(* Logix 5000 project; controller NXEE2_EDS_AOI_Sample_RSLogix_V31 vendor 1 type 14 code 108 rev 31.11; software revision 31.02 *)

TASK MainTask (continuous, watchdog 500 ms) : MainProgram

MODULES
   Local : vendor 1 type 14 code 108 (Compact 0, rev 31.11)
      AMCI_EDS_NXEE2 : vendor 10 type 12 code 50 (Ethernet 192.168.0.50, rev 1.21, StandardDataDriven RPI 8 ms)
END_MODULES

TYPE AMCI_NXEE2_Input_Data :
STRUCT
   Word_0_Reserved_Bit_0 : BOOL;
   Word_0_Reserved_Bit_1 : BOOL;
   CH1_Motion_Detection : BOOL;
   CH1_Velocity_at_Zero : BOOL;
   CH1_Command_Error : BOOL;
   CH1_Config_Error : BOOL;
   CH1_SSI_Setup_Error : BOOL;
   CH1_Scalar_Errors : BOOL;
   CH1_Preset_Value_Error : BOOL;
   CH1_FSC_Error : BOOL;
   CH1_FSC_Exceeded : BOOL;
   Memory_Error : BOOL;
   CH1_Input_State : BOOL;
   CH1_Value_Captured : BOOL;
   Heartbeat : BOOL;
   Acknowledge_Bit : BOOL;
   Word_1_Reserved_Bit_0 : BOOL;
   Word_1_Reserved_Bit_1 : BOOL;
   CH2_Motion_Detection : BOOL;
   CH2_Velocity_at_Zero : BOOL;
   CH2_Command_Error : BOOL;
   CH2_Config_Error : BOOL;
   CH2_SSI_Setup_Error : BOOL;
   CH2_Scalar_Errors : BOOL;
   CH2_Preset_Value_Error : BOOL;
   CH2_FSC_Error : BOOL;
   CH2_FSC_Exceeded : BOOL;
   Word_1_Reserved_bit_11 : BOOL;
   CH2_Input_State : BOOL;
   CH2_Value_Captured : BOOL;
   Word_1_Reserved_bit_14 : BOOL;
   Word_1_Reserved_bit_15 : BOOL;
   CH1_Value_1 : DINT;
   CH1_Value_2 : DINT;
   CH2_Value_1 : DINT;
   CH2_Value_2 : DINT;
END_STRUCT
END_TYPE

TYPE AMCI_NXEE2_Output_Data :
STRUCT
   Command_Word : INT;
   Configuration_Word : INT;
   Number_of_SSI_Data_Bits : INT;
   Number_Of_Data_Value_Bits : SINT;
   MSB_Number : SINT;
   Scalar_Multiplier : INT;
   Scalar_Divisor : INT;
   Preset_Value : DINT;
   Full_Scale_Count : DINT;
END_STRUCT
END_TYPE

ADD_ON_INSTRUCTION NXEE2_Apply_Preset   (* revision 2.0, vendor AMCI, ExecuteEnableInFalse *)
// Revision note:
// 1/29/21 Revision 1.0.  Initial release
// 12/18/2025: Revision 2.0.  Modified the AOIs to use User Defined Input and Output Data
VAR_IN_OUT
   NXEE2_Input_Data : AMCI_NXEE2_Input_Data; {required}
   NXEE2_Output_Data : AMCI_NXEE2_Output_Data; {required}
END_VAR
VAR_INPUT
   Apply_Preset_Ch1_0_NO_1_YES : BOOL; {required}
   Apply_Preset_Ch2_0_NO_1_YES : BOOL; {required}
   Save_In_Flash_0_NO_1_YES : BOOL; {required}
END_VAR
VAR_OUTPUT
   EN : BOOL; {access Read Only, visible}
   DN : BOOL; {access Read Only, visible}
   ER : BOOL; {visible}
END_VAR
VAR
   command_data_block : INT[10];
        [1]   // Setup Word
        [3]   // channel 1 Preset Value
        [7]   // channel 2 Transformation Ratio
        [2]   // channel 1 Full Scale_Count
        [5]   // channel 2 Full Scale Count
        [9]   // Reference Frequency
        [4]   // channel 1 Transformation Ratio
        [0]   // Command Word
        [6]   // channel 2 Preset Value
        [8]   // Reference Voltage
        [0].15   // Transmit bit
   Allow_Programming : BOOL; {access None}
END_VAR

ROUTINE EnableInFalse   (* ladder *)
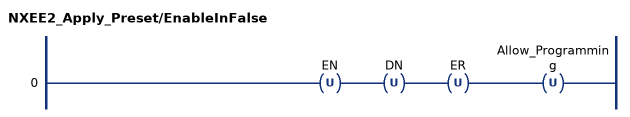
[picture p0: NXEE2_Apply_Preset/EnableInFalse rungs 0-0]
   0: OTU(EN)OTU(DN)OTU(ER)OTU(Allow_Programming);
END_ROUTINE

ROUTINE Logic   (* ladder *)
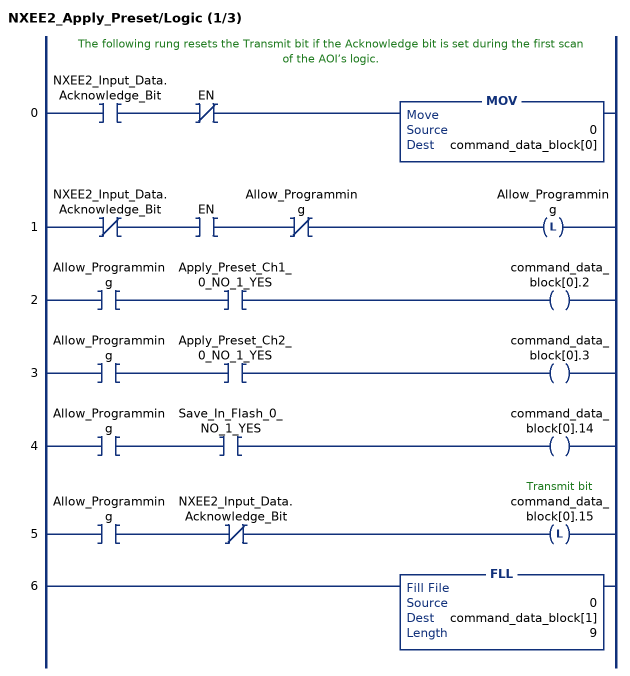
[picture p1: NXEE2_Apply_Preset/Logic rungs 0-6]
   // The following rung resets the Transmit bit if the Acknowledge bit is set during the first scan of the AOI’s logic.
   0: XIC(NXEE2_Input_Data.Acknowledge_Bit)XIO(EN)MOV(0,command_data_block[0]);
   1: XIO(NXEE2_Input_Data.Acknowledge_Bit)XIC(EN)XIO(Allow_Programming)OTL(Allow_Programming);
   2: XIC(Allow_Programming)XIC(Apply_Preset_Ch1_0_NO_1_YES)OTE(command_data_block[0].2);
   3: XIC(Allow_Programming)XIC(Apply_Preset_Ch2_0_NO_1_YES)OTE(command_data_block[0].3);
   4: XIC(Allow_Programming)XIC(Save_In_Flash_0_NO_1_YES)OTE(command_data_block[0].14);
   5: XIC(Allow_Programming)XIO(NXEE2_Input_Data.Acknowledge_Bit)OTL(command_data_block[0].15);
   6: FLL(0,command_data_block[1],9);
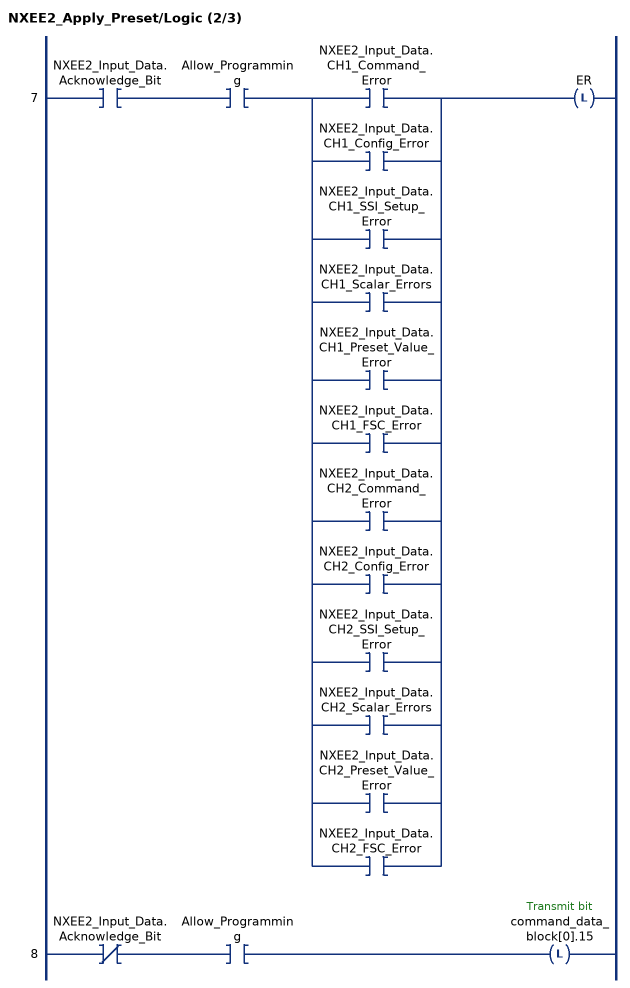
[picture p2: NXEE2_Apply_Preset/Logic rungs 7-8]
   7: XIC(NXEE2_Input_Data.Acknowledge_Bit)XIC(Allow_Programming)[XIC(NXEE2_Input_Data.CH1_Command_Error) ,XIC(NXEE2_Input_Data.CH1_Config_Error) ,XIC(NXEE2_Input_Data.CH1_SSI_Setup_Error) ,XIC(NXEE2_Input_Data.CH1_Scalar_Errors) ,XIC(NXEE2_Input_Data.CH1_Preset_Value_Error) ,XIC(NXEE2_Input_Data.CH1_FSC_Error) ,XIC(NXEE2_Input_Data.CH2_Command_Error) ,XIC(NXEE2_Input_Data.CH2_Config_Error) ,XIC(NXEE2_Input_Data.CH2_SSI_Setup_Error) ,XIC(NXEE2_Input_Data.CH2_Scalar_Errors) ,XIC(NXEE2_Input_Data.CH2_Preset_Value_Error) ,XIC(NXEE2_Input_Data.CH2_FSC_Error) ]OTL(ER);
   8: XIO(NXEE2_Input_Data.Acknowledge_Bit)XIC(Allow_Programming)OTL(command_data_block[0].15);
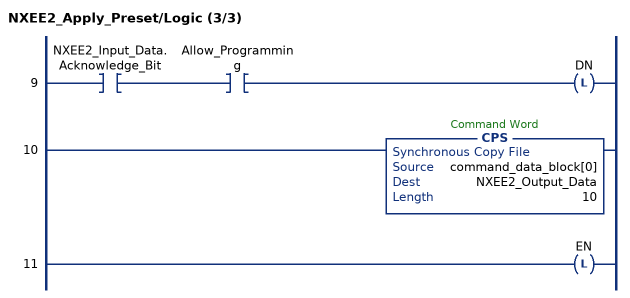
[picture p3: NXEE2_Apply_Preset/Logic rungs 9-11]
   9: XIC(NXEE2_Input_Data.Acknowledge_Bit)XIC(Allow_Programming)OTL(DN);
   10: CPS(command_data_block[0],NXEE2_Output_Data,10);
   11: OTL(EN);
END_ROUTINE
END_ADD_ON_INSTRUCTION

ADD_ON_INSTRUCTION NXEE2_Program_Setup   (* revision 2.0, ExecuteEnableInFalse *)
// Revision note:
// 4/6/2021  Revision 1.0:.  Initial release
// 12/18/2025: Revision 2.0.  Modified the AOIs to use User Defined Input and Output Data.  Also, one setup AOI is now used for both channels.
VAR_IN_OUT
   NXEE2_Input_Data : AMCI_NXEE2_Input_Data; {required}
   NXEE2_Output_Data : AMCI_NXEE2_Output_Data; {required}
END_VAR
VAR_INPUT
   Program_Channel_Number_1_or_2 : INT; {required}
   Network_input_data_format : INT; {required}
   Input_function : INT; {required}
   data_logic_0_positive_1_negative : BOOL; {required}
   data_type_0_binary_1_gray_code : BOOL; {required}
   count_direction_0_normal_1_reverse : BOOL; {required}
   velocity_update_0_160ms_1_24ms : BOOL; {required}
   SSI_Clock_Frequency : INT; {required}
   LED_0_enable_1_disable : BOOL; {required}
   Swap_32_bit_words_endian_0_NO_1_YES : BOOL; {required}
   save_in_flash_0_NO_1_YES : BOOL; {required}
   Number_of_SSI_Clock_Bits : INT; {required}
   MSB_Number : INT; {required}
   Number_of_Data_Value_Bits : INT; {required}
   Scalar_Multiplier : INT; {required}
   Scalar_Divisor : INT; {required}
   Preset_Value : DINT; {required}
   Full_Scale_Count : DINT; {required}
END_VAR
VAR_OUTPUT
   EN : BOOL; {access Read Only, visible}
   DN : BOOL; {access Read Only, visible}
   ER : BOOL; {access Read Only, visible}
END_VAR
VAR
   allow_programming : BOOL;
   command_data_block : INT[10];
        [0].2   // program ch0
        [0].4   // change channel 1 display format
        [0].14   // save in flash
        [0].5   // change channel 2 display format
        [0].15   // transmit bit
        [0].0   // program channel 1
        [0].1   // program channel 2
   internal_preset_value : DINT; {access None}
END_VAR

ROUTINE EnableInFalse   (* ladder *)
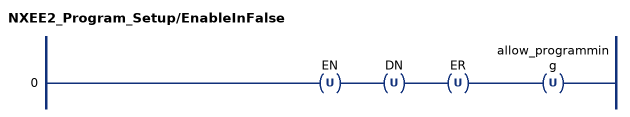
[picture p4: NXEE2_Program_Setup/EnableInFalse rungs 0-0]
   0: OTU(EN)OTU(DN)OTU(ER)OTU(allow_programming);
END_ROUTINE

ROUTINE Logic   (* ladder *)
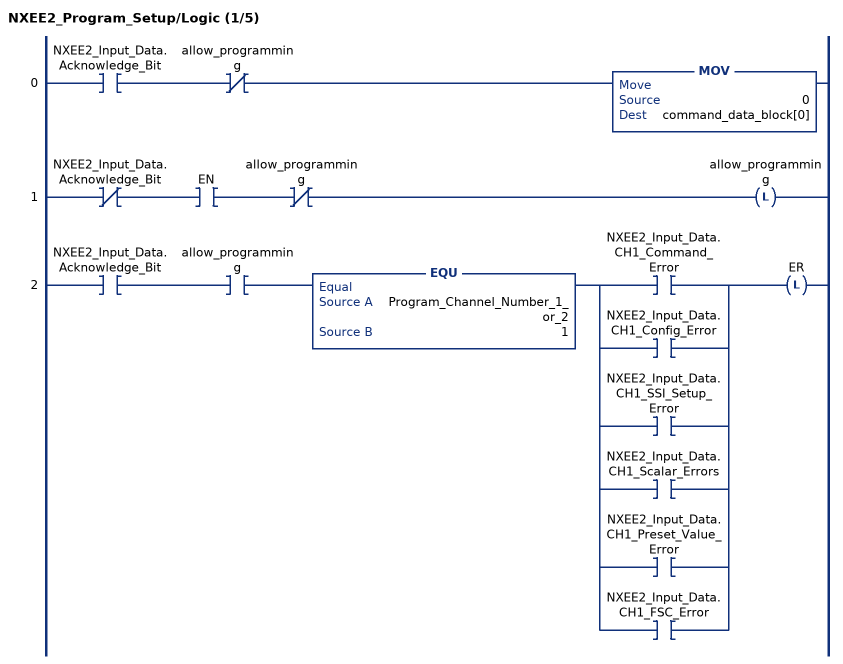
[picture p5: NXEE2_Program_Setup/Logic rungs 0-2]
   0: XIC(NXEE2_Input_Data.Acknowledge_Bit)XIO(allow_programming)MOV(0,command_data_block[0]);
   1: XIO(NXEE2_Input_Data.Acknowledge_Bit)XIC(EN)XIO(allow_programming)OTL(allow_programming);
   2: XIC(NXEE2_Input_Data.Acknowledge_Bit)XIC(allow_programming)EQU(Program_Channel_Number_1_or_2,1)[XIC(NXEE2_Input_Data.CH1_Command_Error) ,XIC(NXEE2_Input_Data.CH1_Config_Error) ,XIC(NXEE2_Input_Data.CH1_SSI_Setup_Error) ,XIC(NXEE2_Input_Data.CH1_Scalar_Errors) ,XIC(NXEE2_Input_Data.CH1_Preset_Value_Error) ,XIC(NXEE2_Input_Data.CH1_FSC_Error) ]OTL(ER);
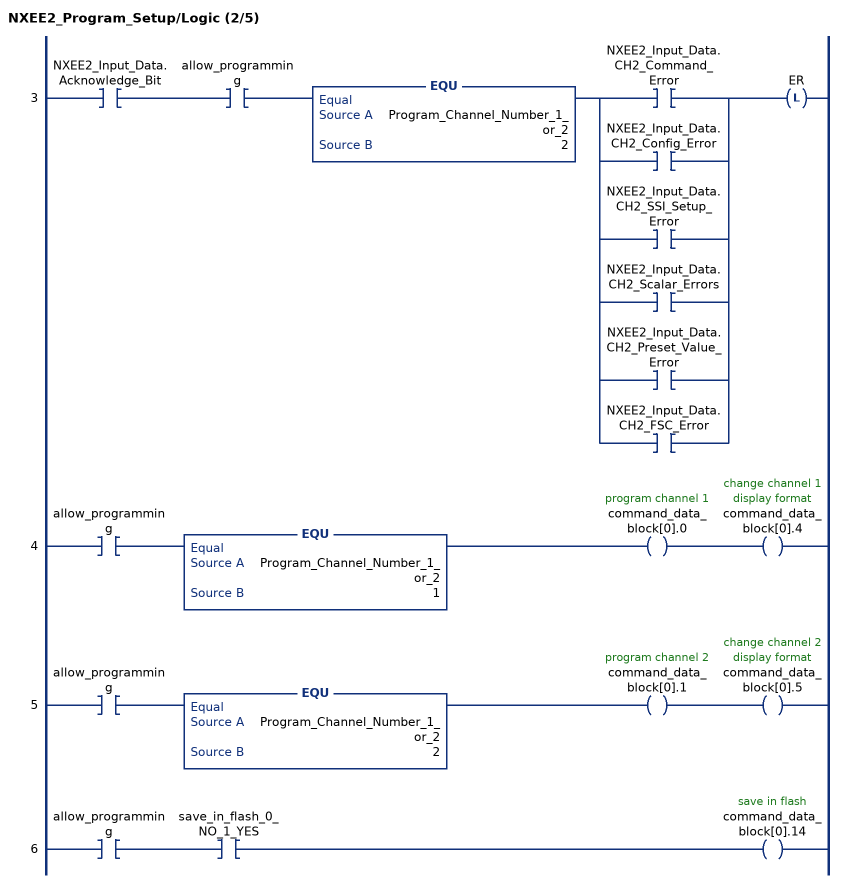
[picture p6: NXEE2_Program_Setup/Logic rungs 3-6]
   3: XIC(NXEE2_Input_Data.Acknowledge_Bit)XIC(allow_programming)EQU(Program_Channel_Number_1_or_2,2)[XIC(NXEE2_Input_Data.CH2_Command_Error) ,XIC(NXEE2_Input_Data.CH2_Config_Error) ,XIC(NXEE2_Input_Data.CH2_SSI_Setup_Error) ,XIC(NXEE2_Input_Data.CH2_Scalar_Errors) ,XIC(NXEE2_Input_Data.CH2_Preset_Value_Error) ,XIC(NXEE2_Input_Data.CH2_FSC_Error) ]OTL(ER);
   4: XIC(allow_programming)EQU(Program_Channel_Number_1_or_2,1)OTE(command_data_block[0].0)OTE(command_data_block[0].4);
   5: XIC(allow_programming)EQU(Program_Channel_Number_1_or_2,2)OTE(command_data_block[0].1)OTE(command_data_block[0].5);
   6: XIC(allow_programming)XIC(save_in_flash_0_NO_1_YES)OTE(command_data_block[0].14);
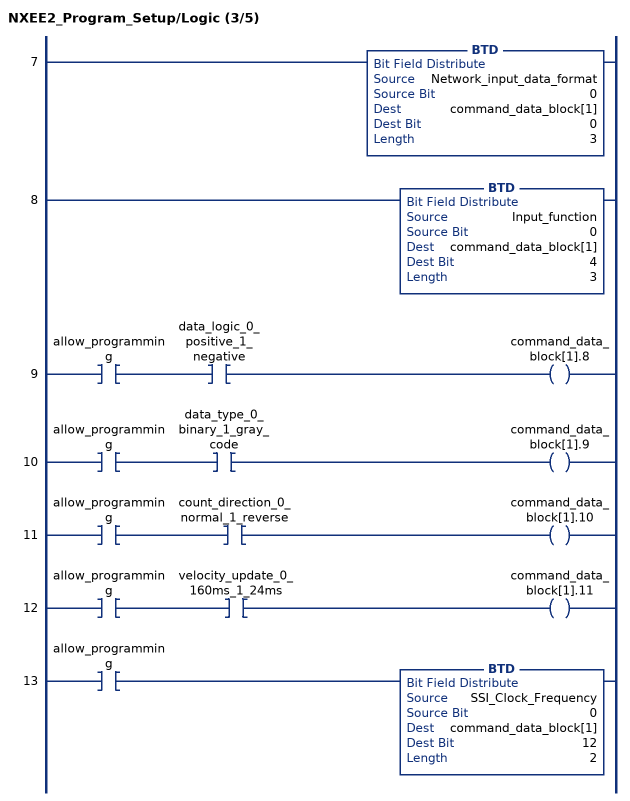
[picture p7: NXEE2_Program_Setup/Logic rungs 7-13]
   7: BTD(Network_input_data_format,0,command_data_block[1],0,3);
   8: BTD(Input_function,0,command_data_block[1],4,3);
   9: XIC(allow_programming)XIC(data_logic_0_positive_1_negative)OTE(command_data_block[1].8);
   10: XIC(allow_programming)XIC(data_type_0_binary_1_gray_code)OTE(command_data_block[1].9);
   11: XIC(allow_programming)XIC(count_direction_0_normal_1_reverse)OTE(command_data_block[1].10);
   12: XIC(allow_programming)XIC(velocity_update_0_160ms_1_24ms)OTE(command_data_block[1].11);
   13: XIC(allow_programming)BTD(SSI_Clock_Frequency,0,command_data_block[1],12,2);
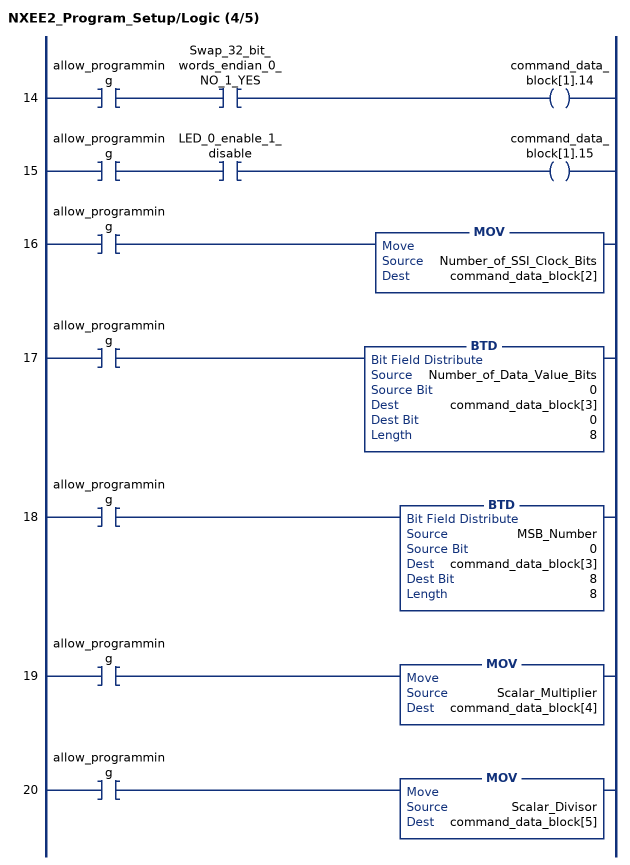
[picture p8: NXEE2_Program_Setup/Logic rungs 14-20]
   14: XIC(allow_programming)XIC(Swap_32_bit_words_endian_0_NO_1_YES)OTE(command_data_block[1].14);
   15: XIC(allow_programming)XIC(LED_0_enable_1_disable)OTE(command_data_block[1].15);
   16: XIC(allow_programming)MOV(Number_of_SSI_Clock_Bits,command_data_block[2]);
   17: XIC(allow_programming)BTD(Number_of_Data_Value_Bits,0,command_data_block[3],0,8);
   18: XIC(allow_programming)BTD(MSB_Number,0,command_data_block[3],8,8);
   19: XIC(allow_programming)MOV(Scalar_Multiplier,command_data_block[4]);
   20: XIC(allow_programming)MOV(Scalar_Divisor,command_data_block[5]);
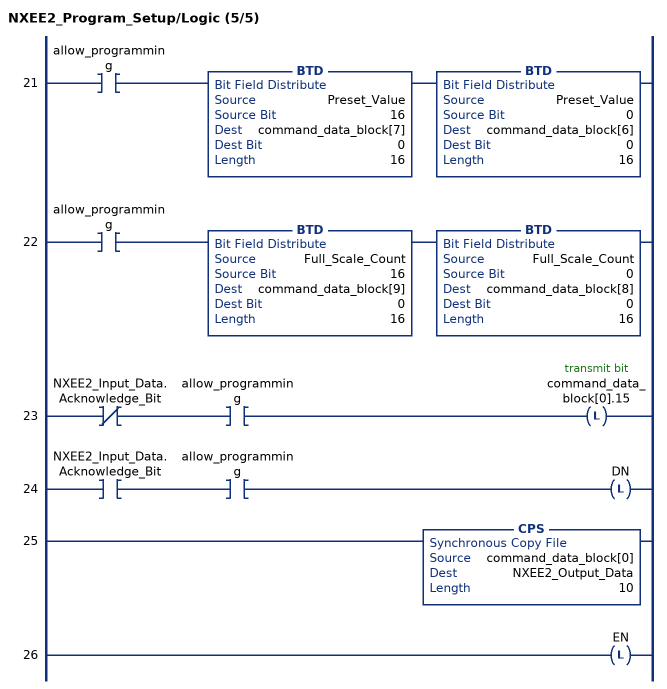
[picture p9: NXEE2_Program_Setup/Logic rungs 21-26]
   21: XIC(allow_programming)BTD(Preset_Value,16,command_data_block[7],0,16)BTD(Preset_Value,0,command_data_block[6],0,16);
   22: XIC(allow_programming)BTD(Full_Scale_Count,16,command_data_block[9],0,16)BTD(Full_Scale_Count,0,command_data_block[8],0,16);
   23: XIO(NXEE2_Input_Data.Acknowledge_Bit)XIC(allow_programming)OTL(command_data_block[0].15);
   24: XIC(NXEE2_Input_Data.Acknowledge_Bit)XIC(allow_programming)OTL(DN);
   25: CPS(command_data_block[0],NXEE2_Output_Data,10);
   26: OTL(EN);
END_ROUTINE
END_ADD_ON_INSTRUCTION

VAR_GLOBAL   (* controller tags *)
   comment_coil : DINT;
   NXEE2_EDS_communication_status : DINT;
   NXEE2_Input_Data : AMCI_NXEE2_Input_Data;
   NXEE2_Output_Data : AMCI_NXEE2_Output_Data;
   Send_EDS_NXEE2 : DINT;   // 1=setup ch1 2=setup ch2 3=apply preset
END_VAR

PROGRAM MainProgram   (* main routine MainRoutine *)
VAR
   NXEE2_EDS_Apply_Preset : NXEE2_Apply_Preset;
   NXEE2_EDS_Setup_CH1 : NXEE2_Program_Setup;
   NXEE2_EDS_Setup_CH2 : NXEE2_Program_Setup;
END_VAR

ROUTINE MainRoutine   (* ladder *)
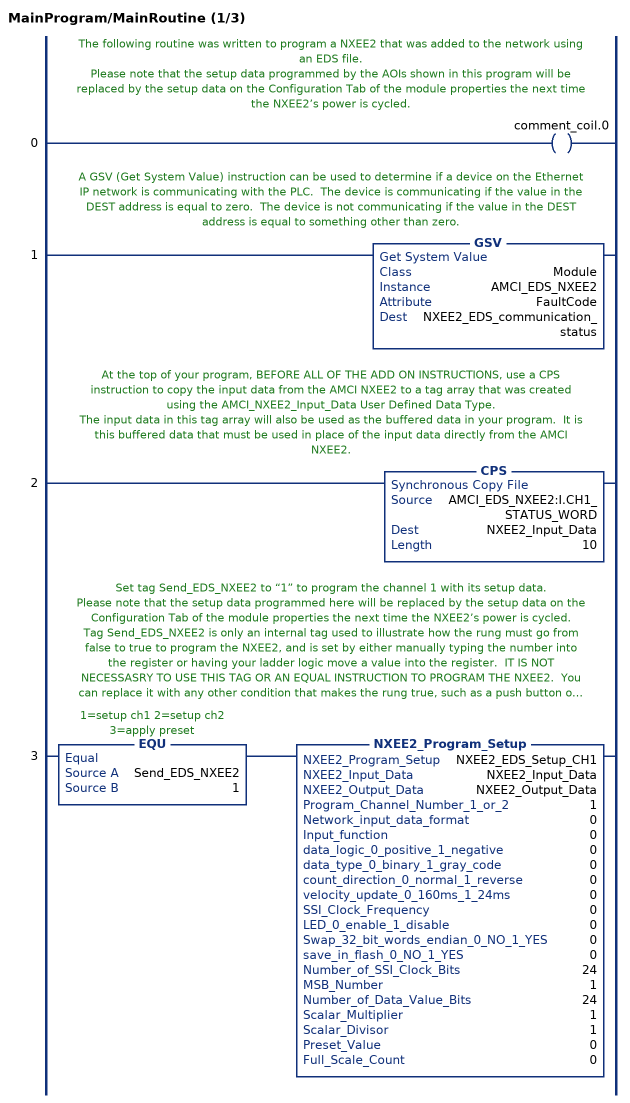
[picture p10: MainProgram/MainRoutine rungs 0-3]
   // The following routine was written to program a NXEE2 that was added to the network using an EDS file.
   // Please note that the setup data programmed by the AOIs shown in this program will be replaced by the setup data on the Configuration Tab of the module properties the next time the NXEE2’s power is cycled.
   0: OTE(comment_coil.0);
   // A GSV (Get System Value) instruction can be used to determine if a device on the Ethernet IP network is communicating with the PLC.  The device is communicating if the value in the DEST address is equal to zero.  The device is not communicating if the value in the DEST address is equal to something other than zero.
   1: GSV(Module,AMCI_EDS_NXEE2,FaultCode,NXEE2_EDS_communication_status);
   // At the top of your program, BEFORE ALL OF THE ADD ON INSTRUCTIONS, use a CPS instruction to copy the input data from the AMCI NXEE2 to a tag array that was created using the AMCI_NXEE2_Input_Data User Defined Data Type.
   // The input data in this tag array will also be used as the buffered data in your program.  It is this buffered data that must be used in place of the input data directly from the AMCI NXEE2.
   2: CPS(AMCI_EDS_NXEE2:I.CH1_STATUS_WORD,NXEE2_Input_Data,10);
   // Set tag Send_EDS_NXEE2 to “1” to program the channel 1 with its setup data.
   // Please note that the setup data programmed here will be replaced by the setup data on the Configuration Tab of the module properties the next time the NXEE2’s power is cycled.
   // Tag Send_EDS_NXEE2 is only an internal tag used to illustrate how the rung must go from false to true to program the NXEE2, and is set by either manually typing the number into the register or having your ladder logic move a value into the register.  IT IS NOT NECESSASRY TO USE THIS TAG OR AN EQUAL INSTRUCTION TO PROGRAM THE NXEE2.  You can replace it with any other condition that makes the rung true, such as a push button on a HMI terminal
   // The following is a list of the available decimal values for the NETWORK INPUT DATA, the INPUT FUNCTION, and the SSI CLOCK FREQUENCIES that can be entered in the setup channel AOI.
   // NETWORK INPUT DATA FORMAT
   // 0=Data Value & Actual SSI
   // 1=Data Value & Velocity
   // 2=Velocity & Actual SSI
   // 3=Data Value & Captured Value
   // 4=Velocity & Captured Value
   // INPUT FUNCTION
   // 0=General Purpose Input
   // 1=Apply Preset on Rising Edge and Save in RAM
   // 2=Apply Preset on Faling Edge and Save in RAM
   // 3=Apply Preset on Both Edges and Save in RAM
   // 4=Capture Data on Rising Edge
   // 5=Capture Data on Falling Edge
   // 6=Capture Data on Both Edges
   // SSI CLOCK FREQUENCY
   // 0=125kHz
   // 1=250kHz
   // 2=500kHZ
   // 3=1MHz
   3: EQU(Send_EDS_NXEE2,1)NXEE2_Program_Setup(NXEE2_EDS_Setup_CH1,NXEE2_Input_Data,NXEE2_Output_Data,1,0,0,0,0,0,0,0,0,0,0,24,1,24,1,1,0,0);
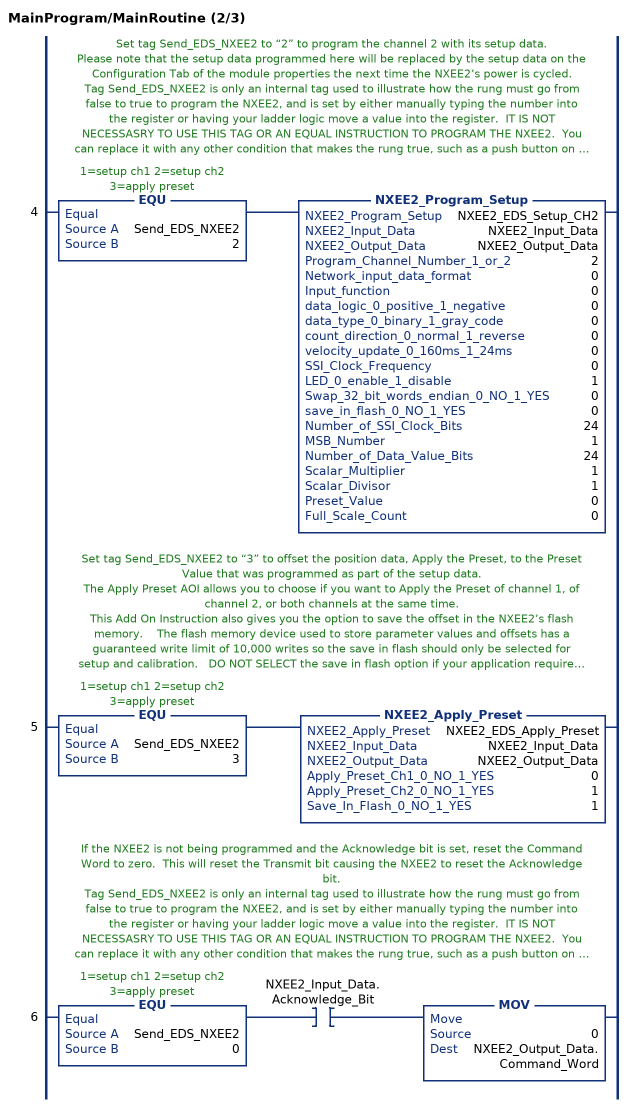
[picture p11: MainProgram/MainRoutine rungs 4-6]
   // Set tag Send_EDS_NXEE2 to “2” to program the channel 2 with its setup data.
   // Please note that the setup data programmed here will be replaced by the setup data on the Configuration Tab of the module properties the next time the NXEE2’s power is cycled.
   // Tag Send_EDS_NXEE2 is only an internal tag used to illustrate how the rung must go from false to true to program the NXEE2, and is set by either manually typing the number into the register or having your ladder logic move a value into the register.  IT IS NOT NECESSASRY TO USE THIS TAG OR AN EQUAL INSTRUCTION TO PROGRAM THE NXEE2.  You can replace it with any other condition that makes the rung true, such as a push button on a HMI terminal
   // The following is a list of the available decimal values for the NETWORK INPUT DATA, the INPUT FUNCTION, and the SSI CLOCK FREQUENCIES that can be entered in the setup channel AOI.
   // NETWORK INPUT DATA FORMAT
   // 0=Data Value & Actual SSI
   // 1=Data Value & Velocity
   // 2=Velocity & Actual SSI
   // 3=Data Value & Captured Value
   // 4=Velocity & Captured Value
   // INPUT FUNCTION
   // 0=General Purpose Input
   // 1=Apply Preset on Rising Edge and Save in RAM
   // 2=Apply Preset on Faling Edge and Save in RAM
   // 3=Apply Preset on Both Edges and Save in RAM
   // 4=Capture Data on Rising Edge
   // 5=Capture Data on Falling Edge
   // 6=Capture Data on Both Edges
   // SSI CLOCK FREQUENCY
   // 0=125kHz
   // 1=250kHz
   // 2=500kHZ
   // 3=1MHz
   4: EQU(Send_EDS_NXEE2,2)NXEE2_Program_Setup(NXEE2_EDS_Setup_CH2,NXEE2_Input_Data,NXEE2_Output_Data,2,0,0,0,0,0,0,0,1,0,0,24,1,24,1,1,0,0);
   // Set tag Send_EDS_NXEE2 to “3” to offset the position data, Apply the Preset, to the Preset Value that was programmed as part of the setup data.
   // The Apply Preset AOI allows you to choose if you want to Apply the Preset of channel 1, of channel 2, or both channels at the same time.
   // This Add On Instruction also gives you the option to save the offset in the NXEE2’s flash memory.    The flash memory device used to store parameter values and offsets has a guaranteed write limit of 10,000 writes so the save in flash should only be selected for setup and calibration.   DO NOT SELECT the save in flash option if your application requires you to constantly preset the position.
   // Tag Send_EDS_NXEE2 is only an internal tag used to illustrate how the rung must go from false to true to program the NXEE2, and is set by either manually typing the number into the register or having your ladder logic move a value into the register.  IT IS NOT NECESSASRY TO USE THIS TAG OR AN EQUAL INSTRUCTION TO PROGRAM THE NXEE2.  You can replace it with any other condition that makes the rung true, such as a push button on a HMI terminal
   5: EQU(Send_EDS_NXEE2,3)NXEE2_Apply_Preset(NXEE2_EDS_Apply_Preset,NXEE2_Input_Data,NXEE2_Output_Data,0,1,1);
   // If the NXEE2 is not being programmed and the Acknowledge bit is set, reset the Command Word to zero.  This will reset the Transmit bit causing the NXEE2 to reset the Acknowledge bit.
   // Tag Send_EDS_NXEE2 is only an internal tag used to illustrate how the rung must go from false to true to program the NXEE2, and is set by either manually typing the number into the register or having your ladder logic move a value into the register.  IT IS NOT NECESSASRY TO USE THIS TAG OR AN EQUAL INSTRUCTION TO PROGRAM THE NXEE2.  You can replace it with any other condition that makes the rung true, such as a push button on a HMI terminal
   6: EQU(Send_EDS_NXEE2,0)XIC(NXEE2_Input_Data.Acknowledge_Bit)MOV(0,NXEE2_Output_Data.Command_Word);
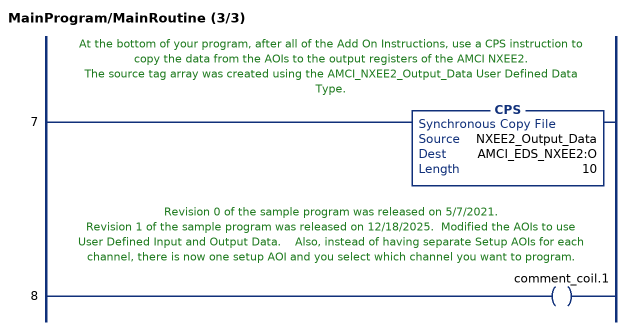
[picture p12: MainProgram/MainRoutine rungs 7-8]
   // At the bottom of your program, after all of the Add On Instructions, use a CPS instruction to copy the data from the AOIs to the output registers of the AMCI NXEE2.
   // The source tag array was created using the AMCI_NXEE2_Output_Data User Defined Data Type.
   7: CPS(NXEE2_Output_Data,AMCI_EDS_NXEE2:O,10);
   // Revision 0 of the sample program was released on 5/7/2021.
   // Revision 1 of the sample program was released on 12/18/2025.  Modified the AOIs to use User Defined Input and Output Data.    Also, instead of having separate Setup AOIs for each channel, there is now one setup AOI and you select which channel you want to program.
   8: OTE(comment_coil.1);
END_ROUTINE
END_PROGRAM
